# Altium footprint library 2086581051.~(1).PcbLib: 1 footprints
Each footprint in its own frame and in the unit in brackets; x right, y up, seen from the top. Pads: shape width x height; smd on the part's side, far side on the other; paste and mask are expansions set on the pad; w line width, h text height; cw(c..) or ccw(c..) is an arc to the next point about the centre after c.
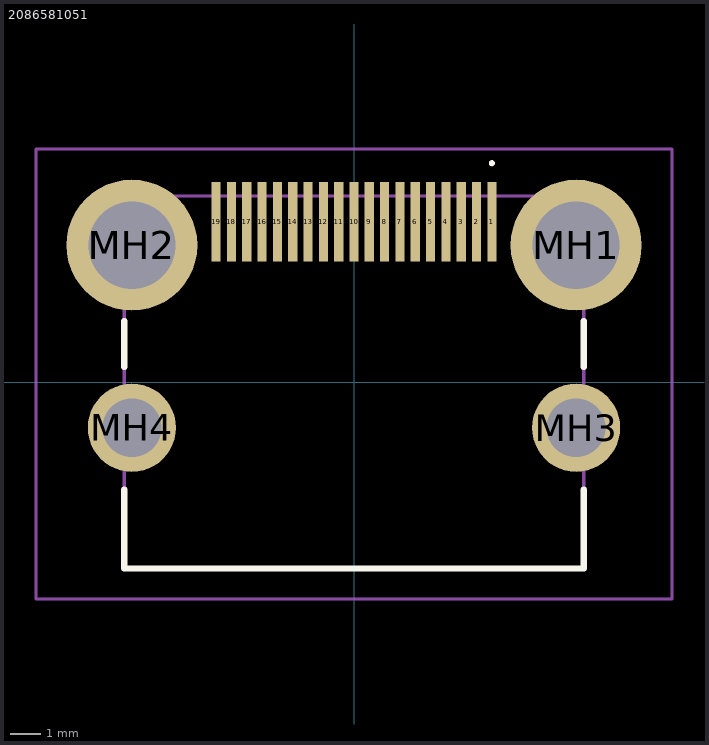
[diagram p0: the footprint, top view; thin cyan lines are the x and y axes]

## 2086581051 [mm]
pads (23):
  rect 0.3x2.6 smd: 1(4.5,5.235) 2(4,5.235) 3(3.5,5.235) 4(3,5.235) 5(2.5,5.235) 6(2,5.235) 7(1.5,5.235) 8(1,5.235) 9(0.5,5.235) 10(0,5.235) 11(-0.5,5.235) 12(-1,5.235) 13(-1.5,5.235) 14(-2,5.235) 15(-2.5,5.235) 16(-3,5.235) 17(-3.5,5.235) 18(-4,5.235) 19(-4.5,5.235)
  round 4.275 hole 2.85: MH1(7.25,4.475) MH2(-7.25,4.475)
  round 2.88 hole 1.92: MH3(7.25,-1.485) MH4(-7.25,-1.485)
Top Overlay:
  lines w0.1: 4.5,7.1 cw(c4.5,7.15) 4.5,7.2 ; 4.5,7.1 4.5,7.1 ; 4.5,7.1 ccw(c4.5,7.15) 4.5,7.2 ; 4.5,7.2 4.5,7.2
  lines w0.2: -7.5,-3.5 -7.5,-6.075 7.5,-6.075 7.5,-3.5 ; -7.5,0.5 -7.5,2 ; 7.5,0.5 7.5,2
Mechanical 15:
  lines w0.1: -7.5,-6.075 7.5,-6.075 7.5,6.075 -7.5,6.075 -7.5,-6.075
Mechanical 20:
  lines w0.1: -10.387,-7.075 10.387,-7.075 10.387,7.612 -10.387,7.612 -10.387,-7.075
